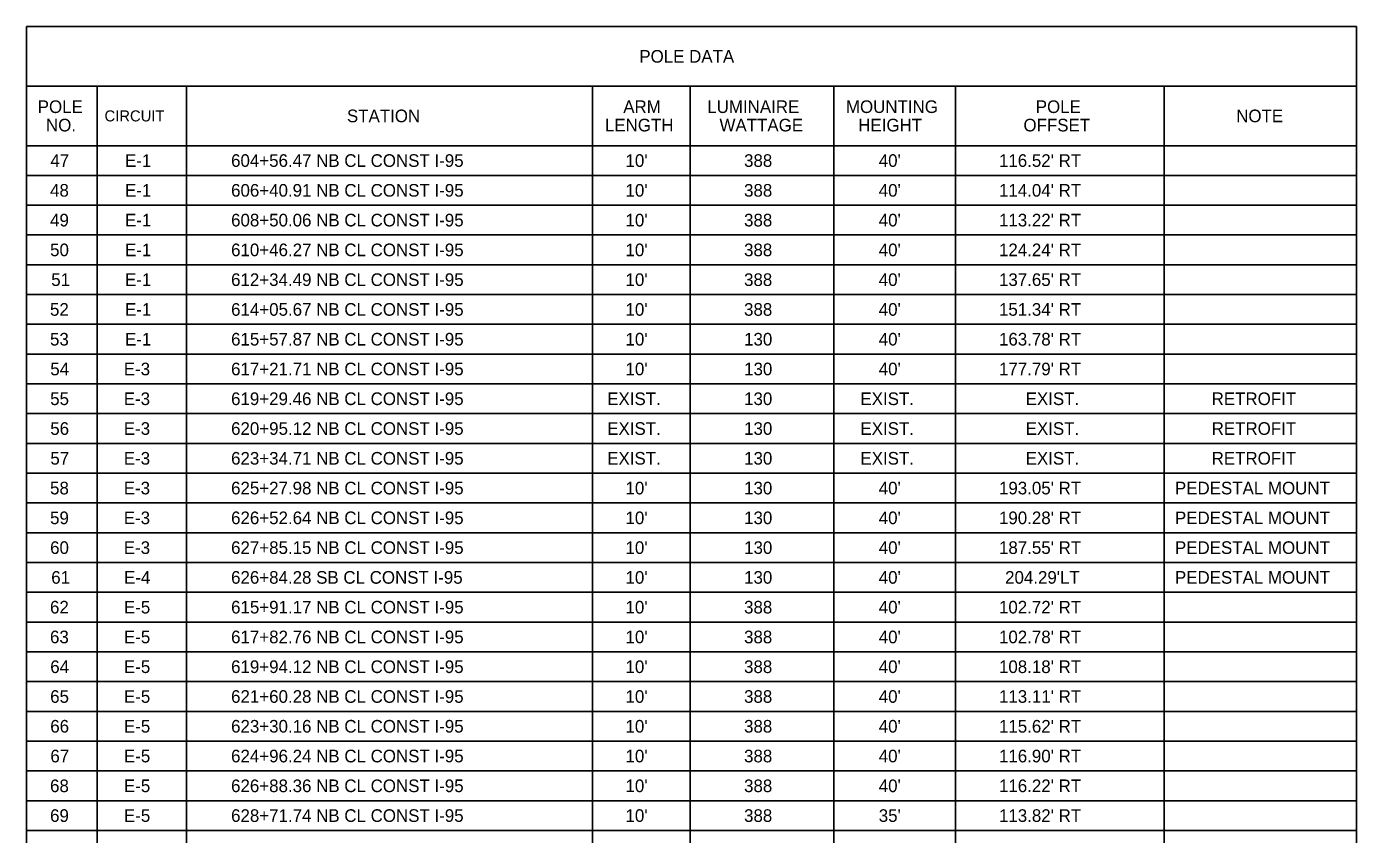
# Model space of a CAD drawing. Extents: x -818.1 to -802.4, y -2221.2 to -2187.7.
# Drawn here: x -809.73 to -802.37, y -2192.17 to -2187.69 of the extents above; entities that cross this region are included whole.
import ezdxf

# ---------------------------------------------------------------- set-up
doc = ezdxf.new("R2010")
doc.units = 0
for name, color, linetype in [('SumBoxBorder_dp', 7, 'Continuous'), ('SumBoxLines_dp', 7, 'Continuous'), ('SumBoxLinesMin_dp', 7, 'Continuous'), ('TextLabel', 7, 'Continuous')]:
    doc.layers.add(name, color=color, linetype=linetype)

msp = doc.modelspace()

# ---------------------------------------------------------------- linework, layer by layer
at = {"layer": 'SumBoxBorder_dp'}
for p, q in [((-809.7339, -2187.6917), (-802.3689, -2187.6917)), ((-809.7339, -2187.6917), (-809.7339, -2195.9417)), ((-802.3689, -2187.6917), (-802.3689, -2195.9417)), ((-809.7339, -2188.0217), (-802.3689, -2188.0217)), ((-809.7339, -2188.0217), (-802.3689, -2188.0217))]:
    msp.add_line(p, q, dxfattribs=at)
at = {"layer": 'SumBoxLines_dp'}
for p, q in [((-809.3439, -2188.0217), (-809.3439, -2195.9417)), ((-809.3439, -2188.0217), (-809.3439, -2195.9417)), ((-808.8489, -2188.0217), (-808.8489, -2195.9417)), ((-808.8489, -2188.0217), (-808.8489, -2195.9417)), ((-806.5989, -2188.0217), (-806.5989, -2188.3517)), ((-806.5989, -2188.0217), (-806.5989, -2195.9417)), ((-806.0589, -2188.0217), (-806.0589, -2195.9417)), ((-806.0589, -2188.0217), (-806.0589, -2195.9417)), ((-805.2639, -2188.0217), (-805.2639, -2195.9417)), ((-805.2639, -2188.0217), (-805.2639, -2195.9417)), ((-804.5889, -2188.0217), (-804.5889, -2195.9417)), ((-804.5889, -2188.0217), (-804.5889, -2195.9417)), ((-803.4339, -2188.0217), (-803.4339, -2195.9417)), ((-803.4339, -2188.0217), (-803.4339, -2195.9417)), ((-809.7339, -2188.3517), (-802.3689, -2188.3517)), ((-808.8489, -2188.3517), (-806.5989, -2188.3517)), ((-806.5989, -2188.5167), (-806.5989, -2192.1467))]:
    msp.add_line(p, q, dxfattribs=at)
at = {"layer": 'SumBoxLinesMin_dp'}
for p, q in [((-809.7339, -2188.3517), (-808.8489, -2188.3517)), ((-806.5989, -2188.3517), (-802.3689, -2188.3517)), ((-809.7339, -2188.5167), (-808.8489, -2188.5167)), ((-809.7339, -2188.5167), (-802.3689, -2188.5167)), ((-806.5989, -2188.5167), (-802.3689, -2188.5167)), ((-809.7339, -2188.6817), (-802.3689, -2188.6817)), ((-809.7339, -2188.6817), (-802.3689, -2188.6817)), ((-809.7339, -2188.8467), (-802.3689, -2188.8467)), ((-809.7339, -2188.8467), (-802.3689, -2188.8467)), ((-809.7339, -2189.0117), (-802.3689, -2189.0117)), ((-809.7339, -2189.0117), (-802.3689, -2189.0117)), ((-809.7339, -2189.1767), (-802.3689, -2189.1767)), ((-809.7339, -2189.1767), (-802.3689, -2189.1767)), ((-809.7339, -2189.3417), (-802.3689, -2189.3417)), ((-809.7339, -2189.3417), (-802.3689, -2189.3417)), ((-809.7339, -2189.5067), (-802.3689, -2189.5067)), ((-809.7339, -2189.5067), (-802.3689, -2189.5067)), ((-809.7339, -2189.6717), (-802.3689, -2189.6717)), ((-809.7339, -2189.6717), (-802.3689, -2189.6717)), ((-809.7339, -2189.8367), (-802.3689, -2189.8367)), ((-809.7339, -2189.8367), (-802.3689, -2189.8367)), ((-809.7339, -2190.0017), (-802.3689, -2190.0017)), ((-809.7339, -2190.0017), (-802.3689, -2190.0017)), ((-809.7339, -2190.1667), (-802.3689, -2190.1667)), ((-809.7339, -2190.1667), (-802.3689, -2190.1667)), ((-809.7339, -2190.3317), (-802.3689, -2190.3317)), ((-809.7339, -2190.3317), (-802.3689, -2190.3317)), ((-809.7339, -2190.4967), (-802.3689, -2190.4967)), ((-809.7339, -2190.4967), (-802.3689, -2190.4967)), ((-809.7339, -2190.6617), (-802.3689, -2190.6617)), ((-809.7339, -2190.6617), (-802.3689, -2190.6617)), ((-809.7339, -2190.8267), (-808.8489, -2190.8267)), ((-809.7339, -2190.8267), (-802.3689, -2190.8267)), ((-806.5989, -2190.8267), (-806.0589, -2190.8267)), ((-805.2639, -2190.8267), (-802.3689, -2190.8267)), ((-809.7339, -2190.9917), (-802.3689, -2190.9917)), ((-809.7339, -2190.9917), (-802.3689, -2190.9917)), ((-809.7339, -2191.1567), (-802.3689, -2191.1567)), ((-809.7339, -2191.1567), (-802.3689, -2191.1567)), ((-809.7339, -2191.3217), (-802.3689, -2191.3217)), ((-809.7339, -2191.3217), (-802.3689, -2191.3217)), ((-809.7339, -2191.4867), (-802.3689, -2191.4867)), ((-809.7339, -2191.4867), (-802.3689, -2191.4867)), ((-809.7339, -2191.6517), (-802.3689, -2191.6517)), ((-809.7339, -2191.6517), (-802.3689, -2191.6517)), ((-809.7339, -2191.8167), (-802.3689, -2191.8167)), ((-809.7339, -2191.8167), (-802.3689, -2191.8167)), ((-809.7339, -2191.9817), (-802.3689, -2191.9817)), ((-809.7339, -2191.9817), (-802.3689, -2191.9817)), ((-809.7339, -2192.1467), (-802.3689, -2192.1467)), ((-809.7339, -2192.1467), (-802.3689, -2192.1467))]:
    msp.add_line(p, q, dxfattribs=at)

# ---------------------------------------------------------------- texts
at = {"layer": 'TextLabel'}
for s, height, p in [('POLE DATA', 0.07, (-806.3403, -2187.8917)), ('POLE', 0.07, (-809.6722, -2188.1707)), ('ARM', 0.07, (-806.4294, -2188.1707)), ('LUMINAIRE', 0.07, (-805.964, -2188.1707)), ('MOUNTING', 0.07, (-805.1961, -2188.1707)), ('POLE', 0.07, (-804.1447, -2188.1707)), ('NO.', 0.07, (-809.6265, -2188.2727)), ('CIRCUIT', 0.06125, (-809.3023, -2188.2173)), ('STATION', 0.07, (-807.9597, -2188.2217)), ('LENGTH', 0.07, (-806.5308, -2188.2727)), ('WATTAGE', 0.07, (-805.8963, -2188.2727)), ('HEIGHT', 0.07, (-805.1279, -2188.2727)), ('OFFSET', 0.07, (-804.2129, -2188.2727)), ('NOTE', 0.07, (-803.0347, -2188.2217)), ('47', 0.07, (-809.6022, -2188.4692)), ('E-1', 0.07, (-809.1888, -2188.4692)), ('604+56.47 NB CL CONST I-95', 0.07, (-808.6013, -2188.4692)), ("10'", 0.07, (-806.4168, -2188.4692)), ('388', 0.07, (-805.7603, -2188.4692)), ("40'", 0.07, (-805.0143, -2188.4692)), ("116.52' RT", 0.07, (-804.3484, -2188.4692)), ('48', 0.07, (-809.6039, -2188.6342)), ('E-1', 0.07, (-809.1888, -2188.6342)), ('606+40.91 NB CL CONST I-95', 0.07, (-808.6013, -2188.6342)), ("10'", 0.07, (-806.4168, -2188.6342)), ('388', 0.07, (-805.7603, -2188.6342)), ("40'", 0.07, (-805.0143, -2188.6342)), ("114.04' RT", 0.07, (-804.3484, -2188.6342)), ('49', 0.07, (-809.6038, -2188.7992)), ('E-1', 0.07, (-809.1888, -2188.7992)), ('608+50.06 NB CL CONST I-95', 0.07, (-808.6013, -2188.7992)), ("10'", 0.07, (-806.4168, -2188.7992)), ('388', 0.07, (-805.7603, -2188.7992)), ("40'", 0.07, (-805.0143, -2188.7992)), ("113.22' RT", 0.07, (-804.3484, -2188.7992)), ('50', 0.07, (-809.6036, -2188.9642)), ('E-1', 0.07, (-809.1888, -2188.9642)), ('610+46.27 NB CL CONST I-95', 0.07, (-808.6013, -2188.9642)), ("10'", 0.07, (-806.4168, -2188.9642)), ('388', 0.07, (-805.7603, -2188.9642)), ("40'", 0.07, (-805.0143, -2188.9642)), ("124.24' RT", 0.07, (-804.3484, -2188.9642)), ('51', 0.07, (-809.5974, -2189.1292)), ('E-1', 0.07, (-809.1888, -2189.1292)), ('612+34.49 NB CL CONST I-95', 0.07, (-808.6013, -2189.1292)), ("10'", 0.07, (-806.4168, -2189.1292)), ('388', 0.07, (-805.7603, -2189.1292)), ("40'", 0.07, (-805.0143, -2189.1292)), ("137.65' RT", 0.07, (-804.3484, -2189.1292)), ('52', 0.07, (-809.6042, -2189.2942)), ('E-1', 0.07, (-809.1888, -2189.2942)), ('614+05.67 NB CL CONST I-95', 0.07, (-808.6013, -2189.2942)), ("10'", 0.07, (-806.4168, -2189.2942)), ('388', 0.07, (-805.7603, -2189.2942)), ("40'", 0.07, (-805.0143, -2189.2942)), ("151.34' RT", 0.07, (-804.3484, -2189.2942)), ('53', 0.07, (-809.6042, -2189.4592)), ('E-1', 0.07, (-809.1888, -2189.4592)), ('615+57.87 NB CL CONST I-95', 0.07, (-808.6013, -2189.4592)), ("10'", 0.07, (-806.4168, -2189.4592)), ('130', 0.07, (-805.76, -2189.4592)), ("40'", 0.07, (-805.0143, -2189.4592)), ("163.78' RT", 0.07, (-804.3484, -2189.4592)), ('54', 0.07, (-809.6028, -2189.6242)), ('E-3', 0.07, (-809.1956, -2189.6242)), ('617+21.71 NB CL CONST I-95', 0.07, (-808.6013, -2189.6242)), ("10'", 0.07, (-806.4168, -2189.6242)), ('130', 0.07, (-805.76, -2189.6242)), ("40'", 0.07, (-805.0143, -2189.6242)), ("177.79' RT", 0.07, (-804.3484, -2189.6242)), ('55', 0.07, (-809.6033, -2189.7892)), ('E-3', 0.07, (-809.1956, -2189.7892)), ('619+29.46 NB CL CONST I-95', 0.07, (-808.6013, -2189.7892)), ('EXIST.', 0.07, (-806.5182, -2189.7892)), ('130', 0.07, (-805.76, -2189.7892)), ('EXIST.', 0.07, (-805.1157, -2189.7892)), ('EXIST.', 0.07, (-804.2007, -2189.7892)), ('RETROFIT', 0.07, (-803.1706, -2189.7892)), ('56', 0.07, (-809.6028, -2189.9542)), ('E-3', 0.07, (-809.1956, -2189.9542)), ('620+95.12 NB CL CONST I-95', 0.07, (-808.6013, -2189.9542)), ('EXIST.', 0.07, (-806.5182, -2189.9542)), ('130', 0.07, (-805.76, -2189.9542)), ('EXIST.', 0.07, (-805.1157, -2189.9542)), ('EXIST.', 0.07, (-804.2007, -2189.9542)), ('RETROFIT', 0.07, (-803.1706, -2189.9542)), ('57', 0.07, (-809.6022, -2190.1192)), ('E-3', 0.07, (-809.1956, -2190.1192)), ('623+34.71 NB CL CONST I-95', 0.07, (-808.6013, -2190.1192)), ('EXIST.', 0.07, (-806.5182, -2190.1192)), ('130', 0.07, (-805.76, -2190.1192)), ('EXIST.', 0.07, (-805.1157, -2190.1192)), ('EXIST.', 0.07, (-804.2007, -2190.1192)), ('RETROFIT', 0.07, (-803.1706, -2190.1192)), ('58', 0.07, (-809.6039, -2190.2842)), ('E-3', 0.07, (-809.1956, -2190.2842)), ('625+27.98 NB CL CONST I-95', 0.07, (-808.6013, -2190.2842)), ("10'", 0.07, (-806.4168, -2190.2842)), ('130', 0.07, (-805.76, -2190.2842)), ("40'", 0.07, (-805.0143, -2190.2842)), ("193.05' RT", 0.07, (-804.3484, -2190.2842)), ('PEDESTAL MOUNT', 0.07, (-803.3739, -2190.2842)), ('59', 0.07, (-809.6038, -2190.4492)), ('E-3', 0.07, (-809.1956, -2190.4492)), ('626+52.64 NB CL CONST I-95', 0.07, (-808.6013, -2190.4492)), ("10'", 0.07, (-806.4168, -2190.4492)), ('130', 0.07, (-805.76, -2190.4492)), ("40'", 0.07, (-805.0143, -2190.4492)), ("190.28' RT", 0.07, (-804.3484, -2190.4492)), ('PEDESTAL MOUNT', 0.07, (-803.3739, -2190.4492)), ('60', 0.07, (-809.6036, -2190.6142)), ('E-3', 0.07, (-809.1956, -2190.6142)), ('627+85.15 NB CL CONST I-95', 0.07, (-808.6013, -2190.6142)), ("10'", 0.07, (-806.4168, -2190.6142)), ('130', 0.07, (-805.76, -2190.6142)), ("40'", 0.07, (-805.0143, -2190.6142)), ("187.55' RT", 0.07, (-804.3484, -2190.6142)), ('PEDESTAL MOUNT', 0.07, (-803.3739, -2190.6142)), ('61', 0.07, (-809.5974, -2190.7792)), ('E-4', 0.07, (-809.1942, -2190.7792)), ('626+84.28 SB CL CONST I-95', 0.07, (-808.6013, -2190.7792)), ("10'", 0.07, (-806.4168, -2190.7792)), ('130', 0.07, (-805.76, -2190.7792)), ("40'", 0.07, (-805.0143, -2190.7792)), ("204.29'LT", 0.07, (-804.3145, -2190.7792)), ('PEDESTAL MOUNT', 0.07, (-803.3739, -2190.7792)), ('62', 0.07, (-809.6042, -2190.9442)), ('E-5', 0.07, (-809.1947, -2190.9442)), ('615+91.17 NB CL CONST I-95', 0.07, (-808.6013, -2190.9442)), ("10'", 0.07, (-806.4168, -2190.9442)), ('388', 0.07, (-805.7603, -2190.9442)), ("40'", 0.07, (-805.0143, -2190.9442)), ("102.72' RT", 0.07, (-804.3484, -2190.9442)), ('63', 0.07, (-809.6042, -2191.1092)), ('E-5', 0.07, (-809.1947, -2191.1092)), ('617+82.76 NB CL CONST I-95', 0.07, (-808.6013, -2191.1092)), ("10'", 0.07, (-806.4168, -2191.1092)), ('388', 0.07, (-805.7603, -2191.1092)), ("40'", 0.07, (-805.0143, -2191.1092)), ("102.78' RT", 0.07, (-804.3484, -2191.1092)), ('64', 0.07, (-809.6028, -2191.2742)), ('E-5', 0.07, (-809.1947, -2191.2742)), ('619+94.12 NB CL CONST I-95', 0.07, (-808.6013, -2191.2742)), ("10'", 0.07, (-806.4168, -2191.2742)), ('388', 0.07, (-805.7603, -2191.2742)), ("40'", 0.07, (-805.0143, -2191.2742)), ("108.18' RT", 0.07, (-804.3484, -2191.2742)), ('65', 0.07, (-809.6033, -2191.4392)), ('E-5', 0.07, (-809.1947, -2191.4392)), ('621+60.28 NB CL CONST I-95', 0.07, (-808.6013, -2191.4392)), ("10'", 0.07, (-806.4168, -2191.4392)), ('388', 0.07, (-805.7603, -2191.4392)), ("40'", 0.07, (-805.0143, -2191.4392)), ("113.11' RT", 0.07, (-804.3484, -2191.4392)), ('66', 0.07, (-809.6028, -2191.6042)), ('E-5', 0.07, (-809.1947, -2191.6042)), ('623+30.16 NB CL CONST I-95', 0.07, (-808.6013, -2191.6042)), ("10'", 0.07, (-806.4168, -2191.6042)), ('388', 0.07, (-805.7603, -2191.6042)), ("40'", 0.07, (-805.0143, -2191.6042)), ("115.62' RT", 0.07, (-804.3484, -2191.6042)), ('67', 0.07, (-809.6022, -2191.7692)), ('E-5', 0.07, (-809.1947, -2191.7692)), ('624+96.24 NB CL CONST I-95', 0.07, (-808.6013, -2191.7692)), ("10'", 0.07, (-806.4168, -2191.7692)), ('388', 0.07, (-805.7603, -2191.7692)), ("40'", 0.07, (-805.0143, -2191.7692)), ("116.90' RT", 0.07, (-804.3484, -2191.7692)), ('68', 0.07, (-809.6039, -2191.9342)), ('E-5', 0.07, (-809.1947, -2191.9342)), ('626+88.36 NB CL CONST I-95', 0.07, (-808.6013, -2191.9342)), ("10'", 0.07, (-806.4168, -2191.9342)), ('388', 0.07, (-805.7603, -2191.9342)), ("40'", 0.07, (-805.0143, -2191.9342)), ("116.22' RT", 0.07, (-804.3484, -2191.9342)), ('69', 0.07, (-809.6038, -2192.0992)), ('E-5', 0.07, (-809.1947, -2192.0992)), ('628+71.74 NB CL CONST I-95', 0.07, (-808.6013, -2192.0992)), ("10'", 0.07, (-806.4168, -2192.0992)), ('388', 0.07, (-805.7603, -2192.0992)), ("35'", 0.07, (-805.0143, -2192.0992)), ("113.82' RT", 0.07, (-804.3484, -2192.0992))]:
    msp.add_text(s, height=height, dxfattribs=at).set_placement(p)

doc.saveas('drawing.dxf')
